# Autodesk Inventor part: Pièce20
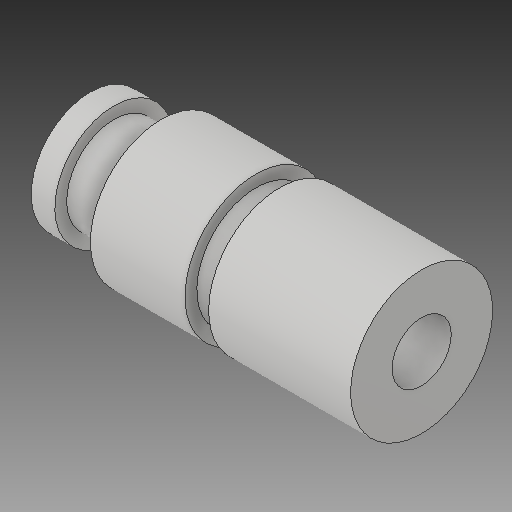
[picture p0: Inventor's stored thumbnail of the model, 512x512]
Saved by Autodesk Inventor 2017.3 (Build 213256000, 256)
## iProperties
Created: 2007-12
Part Number: Pièce20
Material: Générique
Document SubType Name: Modeling
Designer: ficho
Density: 1 g/cm^3
Appearance: Par défaut
Author: ficho
Sending System: SolidWorks 2009
Last Author: christophe
Last Saved: 2011-02-10
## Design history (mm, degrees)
feature "Enlèv. mat.-Extru.1"
node "Solide1"
